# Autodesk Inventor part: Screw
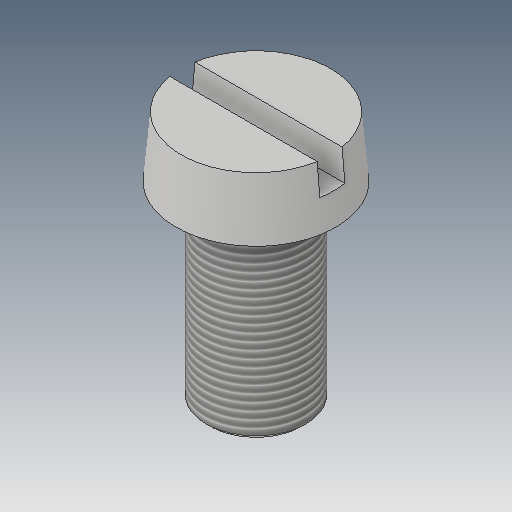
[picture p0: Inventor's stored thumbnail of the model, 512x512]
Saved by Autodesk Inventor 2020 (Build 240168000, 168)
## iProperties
Created: 2016-05
Part Number: Screw
Material: Generic
Document SubType Name: Modeling
Designer: CADCIM
Density: 1 g/cm^3
Appearance: Default
Author: CADCIM
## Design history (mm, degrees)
sketch "Sketch1"
  geometry: C1 r 16 at (0, 0); 1 further point
  constraints: 1 centre point, 1 coincident
  dimensions: "d0" = 32 diameter of C1
extrude "Extrusion1" new body sketch "Sketch1" distance "d1" = 12; taper "d2" = -5 deg
sketch "Sketch2"
  geometry: C1 r 10 at (0, 0); 1 further point
  constraints: 1 centre point, 1 coincident
  dimensions: "d4" = 20 diameter of C1
extrude "Extrusion2" join sketch "Sketch2" distance "d5" = 38; taper "d6" = 0 deg
workplane "Work Plane1"
thread "Thread1" dims "d10" = 10, "d11" = 0
chamfer "Chamfer1" distance "d12" = 0.9; stored, may be unused: second distance "d13" = 2, angle "d14" = 45 deg
sketch "Sketch4"
  geometry: L1 (-19.014, -2.5)-(20.179, -2.5); L2 (20.179, -2.5)-(20.179, 2.5); L3 (20.179, 2.5)-(-19.014, 2.5); L4 (-19.014, 2.5)-(-19.014, -2.5); L5 (0, 0)-(-19.039, 0)
  constraints: 10 end point, 2 horizontal, 2 parallel, 1 perpendicular, 1 other
  dimensions: "d15" = 5 distance of L3.end L1.start
extrude "Extrusion4" cut sketch "Sketch4" distance "d16" = 6; taper "d17" = 0 deg
body "Solid1"
